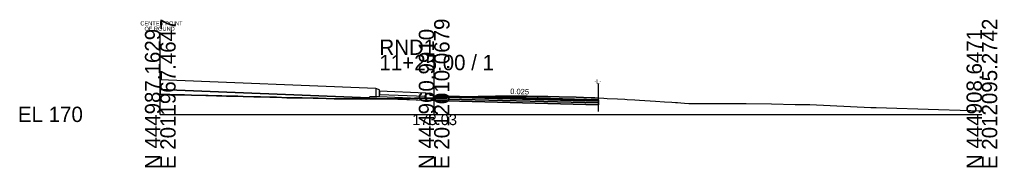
# Model space of a CAD drawing. Extents: x -26 to 153, y -10 to 6017.
# Drawn here: x -25.7 to 152.8, y 2490.3 to 2517.3 of the extents above; entities that cross this region are included whole.
import ezdxf

# ---------------------------------------------------------------- set-up
doc = ezdxf.new("R2010")
doc.units = 0
for name, color, linetype in [('Exist Cross Section Cell', 7, 'Continuous'), ('Exist XS Ground Line', 7, 'Continuous'), ('Prop CMT Conc Surface', 7, 'Continuous'), ('Prop CMT Concrete Structures', 7, 'Continuous'), ('Prop CMT Pvmt Course 1', 7, 'Continuous'), ('Prop CMT Pvmt Course 1 CG', 7, 'Continuous'), ('Prop CMT Pvmt Course 2', 7, 'Continuous'), ('Prop CMT Pvmt Course 3', 7, 'Continuous'), ('Prop CMT Pvmt Surface', 7, 'Continuous'), ('Prop CMT Shear Line', 7, 'Continuous'), ('Prop CMT Shear Line Text', 7, 'Continuous'), ('Prop CMT Slope Grass', 7, 'Continuous'), ('Prop CMT Subgrade Earthwork', 7, 'Continuous'), ('Prop XS Earthwork Shape', 7, 'Continuous'), ('Prop XS SE Text', 7, 'Continuous')]:
    doc.layers.add(name, color=color, linetype=linetype)

msp = doc.modelspace()

# ---------------------------------------------------------------- linework, layer by layer
at = {"layer": 'Exist Cross Section Cell'}
for p, q in [((50, 2500), (50, 2510.86)), ((0, 2500), (50, 2500)), ((50, 2500), (150, 2500))]:
    msp.add_line(p, q, dxfattribs=at)
at = {"layer": 'Exist XS Ground Line'}
msp.add_lwpolyline([(0, 2503.62), (1.19, 2503.61), (2.41, 2503.58), (3.01, 2503.57), (3.99, 2503.55), (4.44, 2503.54), (5.69, 2503.53), (8.3, 2503.45), (8.74, 2503.44), (10.27, 2503.4), (11.22, 2503.37), (12.11, 2503.35), (13.54, 2503.31), (14.16, 2503.29), (15.13, 2503.27), (17.08, 2503.21), (18.31, 2503.19), (20.01, 2503.15), (21.19, 2503.11), (23.1, 2503.04), (24.83, 2503.02), (25.88, 2502.99), (27.9, 2502.95), (28.46, 2502.94), (28.81, 2502.93), (30.27, 2502.89), (31.74, 2502.85), (32.65, 2502.84), (33.88, 2502.84), (34.67, 2502.83), (35.75, 2502.82), (37.78, 2502.82), (40.52, 2502.84), (41.14, 2502.84), (42.09, 2502.86), (43.53, 2502.88), (44.82, 2502.89), (46.42, 2502.93), (46.99, 2502.95), (49.31, 2503.01), (50, 2503.03), (51.67, 2503.07), (52.3, 2503.09), (53.85, 2503.15), (55.23, 2503.19), (55.76, 2503.2), (56.54, 2503.21), (58.17, 2503.23), (59.27, 2503.25), (61.21, 2503.29), (62.95, 2503.31), (64.08, 2503.32), (64.81, 2503.33), (65.92, 2503.33), (67.01, 2503.33), (68.81, 2503.28), (69.97, 2503.26), (70.27, 2503.25), (70.77, 2503.24), (72.84, 2503.19), (75.91, 2503.12), (78.68, 2503.02), (79.36, 2503), (81, 2502.96), (81.61, 2502.92), (83.49, 2502.82), (84.79, 2502.75), (85.21, 2502.73), (86.62, 2502.64), (87.47, 2502.6), (90.42, 2502.41), (92.08, 2502.29), (93.37, 2502.21), (94.09, 2502.17), (94.4, 2502.14), (95.01, 2502.1), (95.7, 2502.05), (96.47, 2502), (96.82, 2501.97), (102.01, 2501.99), (106.55, 2501.97), (106.98, 2501.98), (111.61, 2501.94), (115.94, 2501.81), (118.6, 2501.77), (129.73, 2501.27), (130.71, 2501.24), (142.07, 2500.87), (150, 2500.63)], dxfattribs=at)
at = {"layer": 'Prop CMT Conc Surface'}
for points in [[(40, 2504.4), (39.96, 2504.5), (39.85, 2504.54), (39.34, 2504.73)], [(40, 2504.23), (40, 2504.4)], [(50, 2503.43), (49.25, 2503.45), (49.25, 2503.62), (48.5, 2503.87)]]:
    msp.add_lwpolyline(points, dxfattribs=at)
at = {"layer": 'Prop CMT Concrete Structures'}
for points in [[(40, 2504.4), (39.96, 2504.5), (39.85, 2504.54), (39.34, 2504.73)], [(39.34, 2504.73), (39.34, 2503.23)], [(39.34, 2503.23), (40, 2503.23)], [(40, 2504.23), (40, 2504.4)], [(40, 2503.23), (40, 2504.23)], [(40, 2504.23), (40, 2503.65)], [(48.5, 2503.87), (40, 2504.21)], [(40, 2503.63), (48.5, 2503.29)], [(50, 2503.43), (49.25, 2503.45), (49.25, 2503.62), (48.5, 2503.87)], [(48.5, 2503.87), (48.5, 2502.89)], [(48.5, 2503.29), (48.5, 2503.87)], [(50, 2502.85), (50, 2503.43)], [(48.5, 2502.89), (50, 2502.85)]]:
    msp.add_lwpolyline(points, dxfattribs=at)
at = {"layer": 'Prop CMT Pvmt Course 1'}
for points in [[(50, 2503.43), (80, 2502.68)], [(50, 2503.18), (50, 2503.43)], [(80, 2502.43), (50, 2503.18)], [(80, 2502.68), (80, 2502.43)]]:
    msp.add_lwpolyline(points, dxfattribs=at)
msp.add_lwpolyline([(50, 2503.18), (50, 2503.31), (50, 2503.31), (50, 2503.18)], close=True, dxfattribs=at)
at = {"layer": 'Prop CMT Pvmt Course 1 CG'}
for points in [[(50, 2502.52), (50, 2502.85)], [(80, 2501.76), (80, 2502.1)]]:
    msp.add_lwpolyline(points, dxfattribs=at)
at = {"layer": 'Prop CMT Pvmt Course 2'}
for points in [[(50, 2502.85), (50, 2503.18)], [(50, 2503.18), (80, 2502.43)], [(80, 2502.1), (50, 2502.85)], [(80, 2502.43), (80, 2502.1)]]:
    msp.add_lwpolyline(points, dxfattribs=at)
at = {"layer": 'Prop CMT Pvmt Course 3'}
for points in [[(40, 2503.23), (48.5, 2502.89)], [(50, 2502.85), (80, 2502.1)], [(50, 2502.52), (50, 2502.85)], [(80, 2501.76), (50, 2502.52)], [(80, 2502.1), (80, 2501.76)]]:
    msp.add_lwpolyline(points, dxfattribs=at)
at = {"layer": 'Prop CMT Pvmt Surface'}
msp.add_lwpolyline([(50, 2503.43), (80, 2502.68)], dxfattribs=at)
at = {"layer": 'Prop CMT Shear Line'}
for p, q in [((0, 2499.97), (0, 2514.97)), ((80, 2500.51), (80, 2505.52))]:
    msp.add_line(p, q, dxfattribs=at)
at = {"layer": 'Prop CMT Slope Grass'}
for p, q in [((39.34, 2504.71), (0, 2506.28)), ((38.06, 2503), (0, 2504.52))]:
    msp.add_line(p, q, dxfattribs=at)
at = {"layer": 'Prop CMT Subgrade Earthwork'}
for p, q in [((0, 2506.28), (0, 2503.62)), ((38.34, 2503.27), (38.06, 2503)), ((80, 2501.76), (80, 2502.98))]:
    msp.add_line(p, q, dxfattribs=at)
for points in [[(38.34, 2503.27), (39.34, 2503.23)], [(38.06, 2503), (50, 2502.52)], [(50, 2502.52), (80, 2501.76)]]:
    msp.add_lwpolyline(points, dxfattribs=at)
at = {"layer": 'Prop XS Earthwork Shape'}
for points in [[(38.06, 2503), (41.72, 2502.85), (41.14, 2502.84), (40.52, 2502.84), (37.78, 2502.82), (35.75, 2502.82), (34.67, 2502.83), (33.88, 2502.84), (32.65, 2502.84), (31.74, 2502.85), (30.27, 2502.89), (28.81, 2502.93), (28.46, 2502.94), (27.9, 2502.95), (25.88, 2502.99), (24.83, 2503.02), (23.1, 2503.04), (21.19, 2503.11), (20.01, 2503.15), (18.31, 2503.19), (17.08, 2503.21), (15.13, 2503.27), (14.16, 2503.29), (13.54, 2503.31), (12.11, 2503.35), (11.22, 2503.37), (10.27, 2503.4), (8.74, 2503.44), (8.3, 2503.45), (5.69, 2503.53), (4.44, 2503.54), (3.99, 2503.55), (3.01, 2503.57), (2.41, 2503.58), (1.19, 2503.61), (0, 2503.62), (0, 2504.52)], [(48.5, 2502.89), (48.5, 2502.99), (46.99, 2502.95), (46.42, 2502.93), (44.82, 2502.89), (43.53, 2502.88), (42.09, 2502.86), (41.72, 2502.85), (50, 2502.52), (80, 2501.76), (80, 2502.68), (58.06, 2503.23), (56.54, 2503.21), (55.76, 2503.2), (55.23, 2503.19), (53.85, 2503.15), (52.3, 2503.09), (51.67, 2503.07), (50, 2503.03), (50, 2502.85)], [(48.5, 2502.89), (48.5, 2502.99), (49.31, 2503.01), (50, 2503.03), (50, 2502.85)], [(80, 2502.68), (80, 2502.98), (79.36, 2503), (78.68, 2503.02), (75.91, 2503.12), (72.84, 2503.19), (70.77, 2503.24), (70.27, 2503.25), (69.97, 2503.26), (68.81, 2503.28), (67.01, 2503.33), (65.92, 2503.33), (64.81, 2503.33), (64.08, 2503.32), (62.95, 2503.31), (61.21, 2503.29), (59.27, 2503.25), (58.17, 2503.23), (58.06, 2503.23)]]:
    msp.add_lwpolyline(points, close=True, dxfattribs=at)

# ---------------------------------------------------------------- texts
at = {"layer": 'Exist Cross Section Cell'}
for s, p in [('E 2011967.4647', (2.8, 2490)), ('E 2012010.0679', (52.8, 2490)), ('E 2012095.2742', (152.8, 2490)), ('N 444987.1629', (0, 2490)), ('N 444960.9910', (50, 2490)), ('N 444908.6471', (150, 2490))]:
    msp.add_text(s, height=2.8, rotation=90, dxfattribs=at).set_placement(p)
for s, p in [('RND1', (40, 2510.86)), ('11+25.00 / 1', (40, 2508.06)), ('EL 170', (-26, 2498.6))]:
    msp.add_text(s, height=2.8, dxfattribs=at).set_placement(p)
at = {"layer": 'Exist XS Ground Line'}
msp.add_text('173.03', height=2, dxfattribs=at).set_placement((45.99, 2498.03))
at = {"layer": 'Prop CMT Shear Line Text'}
for s, p in [('CENTER POINT', (-3.64, 2516.23)), ('OF ROUND', (-2.88, 2515.25)), ('-L-', (79.27, 2505.63))]:
    msp.add_text(s, height=0.75, dxfattribs=at).set_placement(p)
at = {"layer": 'Prop XS SE Text'}
msp.add_text('0.025', height=1, rotation=358.5613, dxfattribs=at).set_placement((63.87, 2503.71))

doc.saveas('drawing.dxf')
